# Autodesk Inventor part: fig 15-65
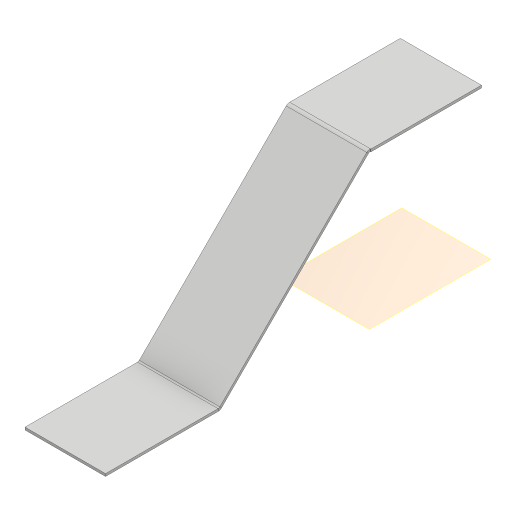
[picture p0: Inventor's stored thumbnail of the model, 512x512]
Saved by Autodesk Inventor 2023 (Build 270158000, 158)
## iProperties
Created: 2015-07
Part Number: fig 15-65
Material: Generic
Document SubType Name: Sheet Metal
Designer: Sandeep
Density: 1 g/cm^3
Sheet Metal Rule: Default_mm
Appearance: Default
Author: Sandeep
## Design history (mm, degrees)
sketch "Sketch1"
  geometry: L1 (0, 0)-(16.327, 0); L2 (16.327, 0)-(16.327, 22.261); L3 (16.327, 22.261)-(0, 22.261); L4 (0, 22.261)-(0, 0)
  constraints: 8 end point, 2 parallel, 1 horizontal, 1 perpendicular
workplane "Work Plane1"
sketch "Sketch2"
  geometry: L1 (0, -53.275)-(16.202, -53.275); L2 (16.202, -53.275)-(16.202, -30.325); L3 (16.202, -30.325)-(0, -30.325); L4 (0, -30.325)-(0, -53.275); 1 further point
  constraints: 8 end point, 2 parallel, 1 horizontal, 1 perpendicular
node "Face1"
node "Face2"
bend "Bend2" dims "d7" = 0.5 (= BendReliefWidth), "d8" = 0.25 (= BendReliefDepth), "d9" = 1 (= MinimumRemnant), "d10" = 0.5 (= BendRadius), "d11" = 0.5 (= BendRadius), "d12" = 0.5 (= Thickness), "SeamGap" = 0.01
body "Solid1"
face "Plate1" dims "d12" = 0.5 (= Thickness)
face "Plate2" dims "d2" = 0.5 (= BendRadius), "d3" = 0.5 (= BendReliefWidth), "d5" = 1 (= MinimumRemnant), "d12" = 0.5 (= Thickness)
bend "Bend1" dims "d2" = 0.5 (= BendRadius), "d3" = 0.5 (= BendReliefWidth), "d4" = 0.25 (= BendReliefDepth), "d5" = 1 (= MinimumRemnant), "d6" = 0.5 (= BendRadius), "d12" = 0.5 (= Thickness), "SeamGap" = 0.01
other parameters: "Thickness" = 0.5, "BendRadius" = 0.5 (= Thickness), "BendReliefWidth" = 0.5 (= Thickness), "BendReliefDepth" = 0.25 (= 0.5 x Thickness), "CornerReliefSize" = 2 (= 4 x Thickness), "MinimumRemnant" = 1 (= 2 x Thickness), "TransitionRadius" = 0.5 (= BendRadius), "JacobiRadiusSize" = 0.5 (= BendRadius), "GapSize" = 0.5 (= Thickness), "d1" = 0.5 (= BendRadius)
